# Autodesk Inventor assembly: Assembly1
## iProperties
Shininess: 64.0
Length Units: 11269
Angle Units: 11279
Time Units: 11290
Mass Units: 11283
Length Display Precision: 3
Angle Display Precision: 2
Created: 2002-01
Part Number: Assembly1
Document SubType Name: Assembly
Designer: ***
Density: 0.0
Volumn: 0.0
Area: 0.0
PropertySet Name: Model Information
Control State: 0
Master: False
Checked Out: False
Author: ***
